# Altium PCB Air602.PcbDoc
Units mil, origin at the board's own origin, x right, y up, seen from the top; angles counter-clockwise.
Board outline 6000 x 4000 mil, 2 copper layers (Top, Bottom), stack 12.7 mil thick; 1 components, 0 nets, 12 pads, 0 vias.
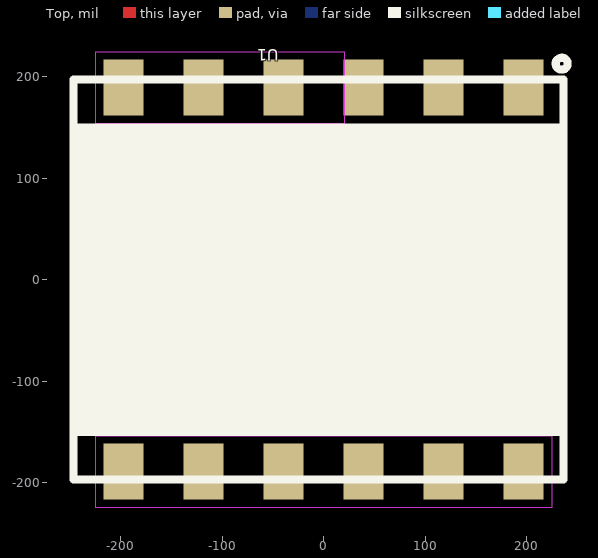
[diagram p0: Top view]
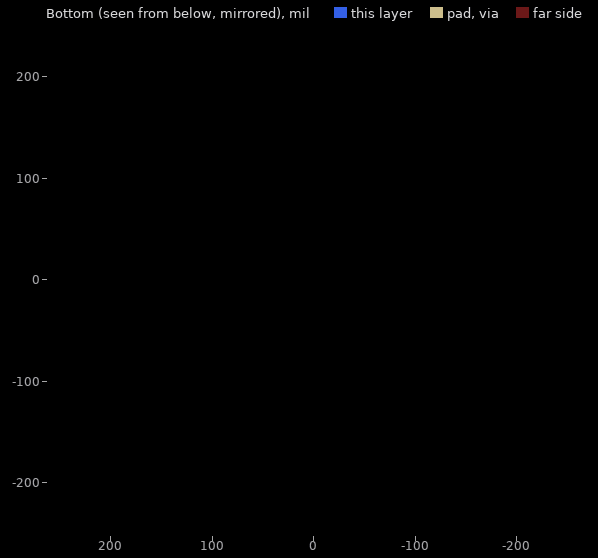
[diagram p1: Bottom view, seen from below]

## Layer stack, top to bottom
Solder Mask Top: solder mask 0.4, Solder Resist, Dk 3.5
Top: signal copper 1.35
Dielectric 1: dielectric 10, FR-4, Dk 4.3
Bottom: signal copper 1.35
Solder Mask Bottom: solder mask 0.4, Solder Resist, Dk 3.5

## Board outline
-9000,-9000 -3000,-9000 -3000,-5000 -9000,-5000

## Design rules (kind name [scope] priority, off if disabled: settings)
Clearance "Clearance - Default - DEFAULT- SMD" [IsVia vs IsSMTPin] p1: gap=6 ignorepadtopadclearanceinfootprint=FALSE
Clearance "Clearance - Default - DEFAULT - Via" [IsVia vs IsVia] p2: gap=6 ignorepadtopadclearanceinfootprint=FALSE
Clearance "Clearance - Default - DEFAULT - Net" [All] p3: gap=6 ignorepadtopadclearanceinfootprint=FALSE except(0: Arc-Hole Track-Hole SMDPad-Hole THPad-Hole Via-Hole Fill-Hole Poly-Hole Region-Hole Text-Hole; 10: Text-Text)
ComponentClearance "ComponentClearance - Default - DEFAULT" [All] p1: gap=6 collisioncheckmode=3 verticalgap=10 showdistances=FALSE
FanoutControl Fanout_Small [(CompPinCount < 5)] p3: bgadir=Out bgaviamode=Centered fanoutstyle=Auto fanoutdirection=OutThenIn viagrid=1 // Fanout_Small (Default Rule)
FanoutControl Fanout_SOIC [IsSOIC] p4: bgadir=Out bgaviamode=Centered fanoutstyle=Auto fanoutdirection=Alternating viagrid=1 // Fanout_SOIC (Default Rule)
HoleToHoleClearance "HoleToHoleClearance - Default - DEFAULT" [All] p1: gap=6 allowstackedmicrovias=TRUE
Length "Default Length" [All] p1: maxlimit=50000 minlimit=0
MaxMinImpedance "Default Impedance" [All] p1: minimum=50.00 maximum=150.0
ParallelSegment "Default Parallel Segment Adjasent" [All] p1: limit=1000 gap=200
ParallelSegment "Default Parallel Segment Same Layer" [All] p2: limit=1000 gap=200
PlaneConnect "Default PlaneConnect" [All] p1: planeconnectstyle=Relief reliefexpansion=20 reliefentries=0 reliefconductorwidth=15 reliefairgap=10
PolygonConnect "PolygonConnect - Default SMT" [IsSMTPin] p1: connectstyle=Relief reliefconductorwidth=10 reliefentries=4 polygonreliefangle="45 Angle" airgapwidth=10
PolygonConnect "PolygonConnect - Default Pad" [All] p2: connectstyle=Relief reliefconductorwidth=15 reliefentries=4 polygonreliefangle="45 Angle" airgapwidth=10
RoutingLayers "RoutingLayers - Default - DEFAULT" [All] p1: top layer_v5=TRUE bottom layer_v5=TRUE
RoutingPriority "RoutingPriority - Default - DEFAULT" [All] p1: routingpriority=3
RoutingTopology "Default Routing Topology" [All] p1: topology=Shortest
RoutingVias "RoutingVias - Default - DEFAULT" [All] p1: holewidth=37 width=55 viastyle="Through Hole" minholewidth=37 minwidth=55 maxholewidth=37 maxwidth=55
SMDToCorner "SMDToCorner - Default - DEFAULT" [All] p1: distance=60000
SolderMaskExpansion [All] p1: expansion=4
Width "Default Width" [All] p1: maxlimit=12 minlimit=12 preferedwidth=12
22 further rules are at their usual default settings.

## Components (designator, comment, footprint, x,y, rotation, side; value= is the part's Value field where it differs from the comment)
U1 "WMIOT602" WMIOT602 0,0 r270 top

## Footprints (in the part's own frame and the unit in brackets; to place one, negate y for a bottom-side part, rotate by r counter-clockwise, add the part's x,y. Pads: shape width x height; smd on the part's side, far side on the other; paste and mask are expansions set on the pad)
WMIOT602 [mm]
  rect 1.4x1 smd: 1(-4.8,5) 2(-4.8,3) 3(-4.8,1) 4(-4.8,-1) 5(-4.8,-3) 6(-4.8,-5) 7(4.8,-5) 8(4.8,-3) 9(4.8,-1) 10(4.8,1) 11(4.8,3) 12(4.8,5)
  Top keep-out region: -5.7,0.514 -3.9,0.514 -3.9,-5.7 -5.7,-5.7 -5.7,0.514
  Top keep-out region: 3.9,5.7 5.7,5.7 5.7,-5.7 3.9,-5.7 3.9,5.7
  silkscreen extent -5.55,-6.25 5,6.1

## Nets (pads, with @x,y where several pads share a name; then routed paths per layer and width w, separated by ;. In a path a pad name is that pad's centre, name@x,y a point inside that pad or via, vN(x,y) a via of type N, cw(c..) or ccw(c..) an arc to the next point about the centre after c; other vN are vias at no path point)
pads on no net: U1.1 U1.2 U1.3 U1.4 U1.5 U1.6 U1.7 U1.8 U1.9 U1.10 U1.11 U1.12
